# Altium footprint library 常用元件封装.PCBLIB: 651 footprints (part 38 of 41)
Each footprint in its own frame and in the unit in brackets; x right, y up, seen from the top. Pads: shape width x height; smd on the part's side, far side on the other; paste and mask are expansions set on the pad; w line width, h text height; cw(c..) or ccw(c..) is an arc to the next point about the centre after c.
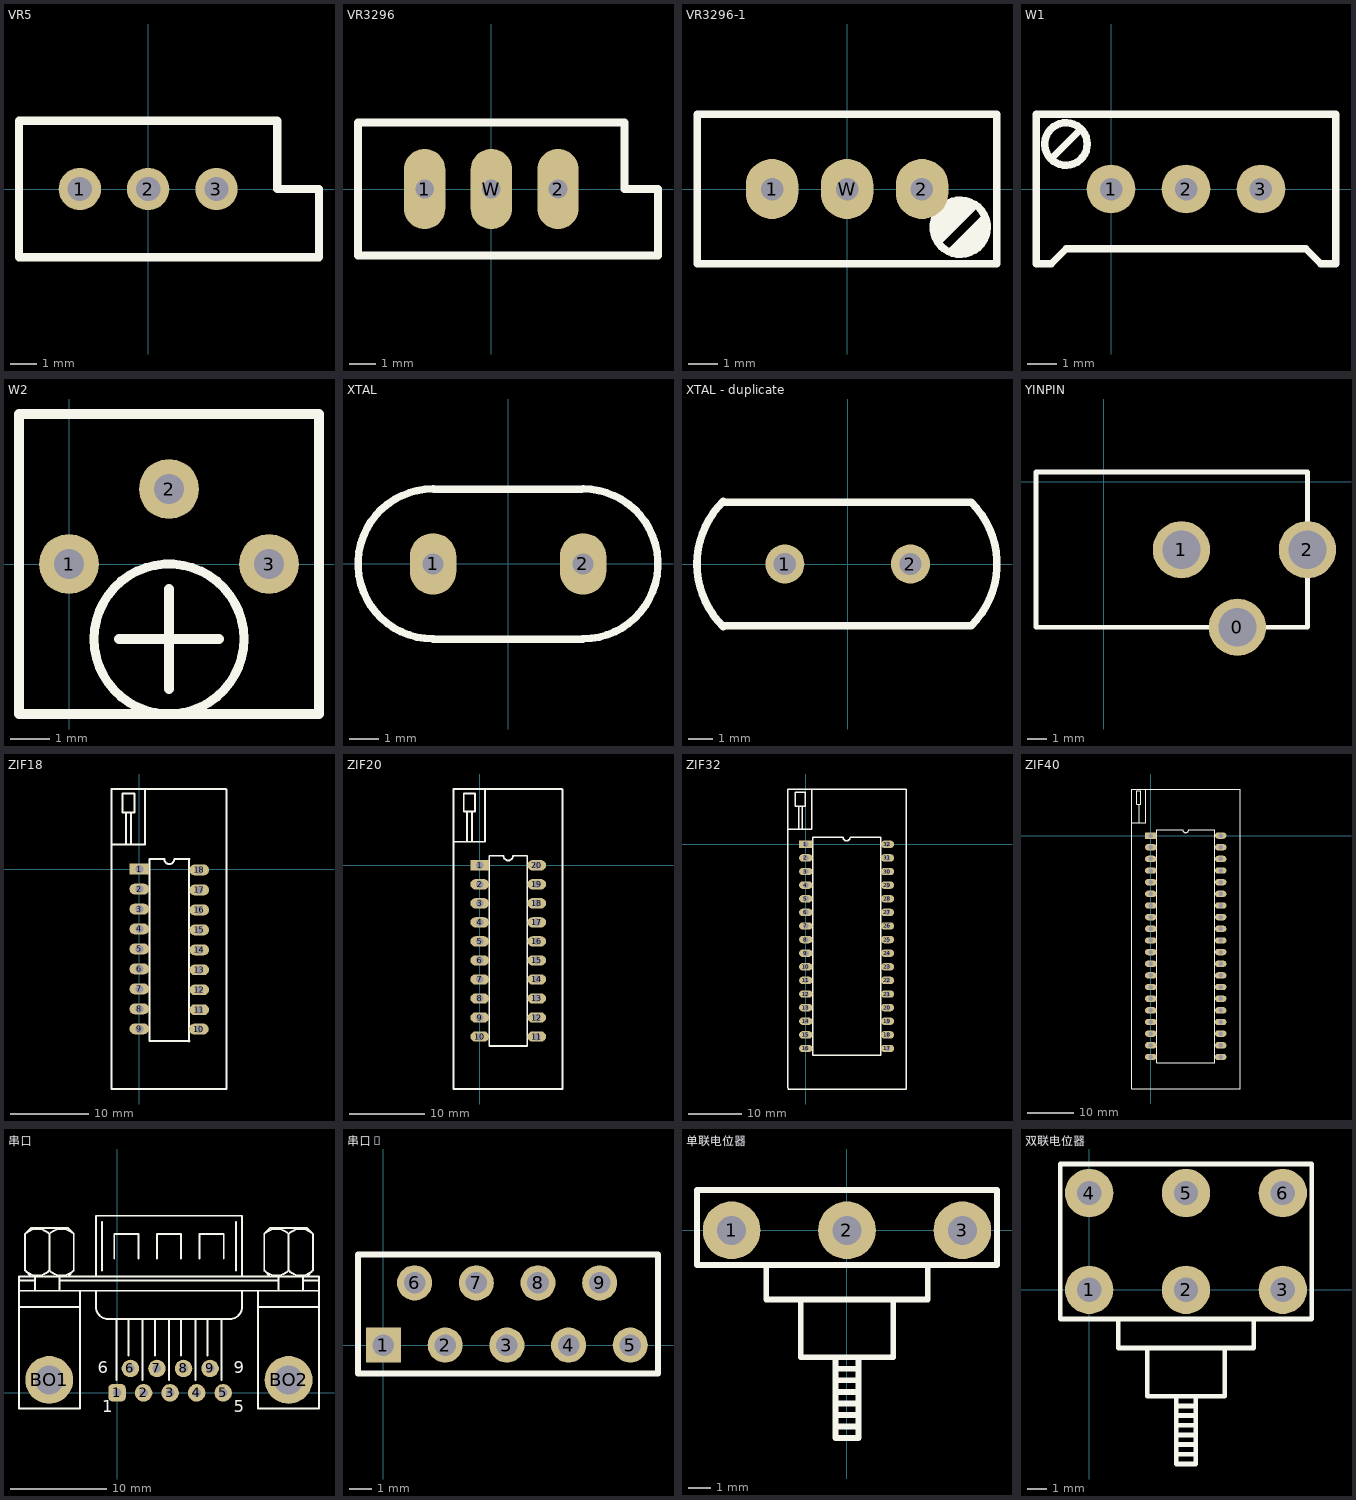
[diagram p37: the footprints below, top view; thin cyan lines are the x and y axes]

## VR5 [mil]
pads (3):
  round 62 hole 35.43: 1(-100,0) 2(0,0) 3(100,0)
TopOverlay:
  lines w12: -188.98,-100 -188.98,100 188.98,100 188.98,0 250,0 250,-100 -188.98,-100

## VR3296 [mil]
pads (3):
  oval 62x120 hole 28: 1(-100,0) 2(100,0) W(0,0)
TopOverlay:
  lines w12: -200,-100 250,-100 250,0 200,0 200,100 -200,100 -200,-100

## VR3296-1 [mil]
pads (3):
  oval 70x80 hole 30: 1(-100,0) 2(100,0) W(0,0)
TopOverlay:
  circle w10: c151,-51 r36.06
  lines w10: 157.76,-74.24 164.24,-74.24 171,-81 ; 171,-21 151,-41 121,-71 121,-61 161,-21 141,-21 ; 172.88,-79.12 171,-81 ; 181,-41 141,-81 151,-81 ; 131,-31 121,-41 121,-51 141,-31 ; 131,-31 141,-21 ; 131,-31 141,-31 ; 141,-31 141,-21 ; 141,-31 151,-31 141,-21 ; 151,-81 171,-81 ; 151,-81 166.82,-65.18 172.88,-65.18 187.06,-51 187.06,-47.06 172.88,-61.23 170.77,-61.23 171,-61.47 171,-81 ; -200,-100 0,-100 200,-100 200,100 -200,100 -200,-100

## W1 [mil] "3296"
pads (3):
  round 65 hole 30: 1(0,0) 2(100,0) 3(200,0)
TopOverlay:
  circle w10: c-60,60 r28.28
  lines w10: -80,40 -40,80 ; -100,-100 -80,-100 -60,-80 260,-80 280,-100 300,-100 300,100 -100,100 -100,-100

## W2 [mil]
pads (3):
  round 60 hole 30: 1(0,0) 2(100,75) 3(200,0)
TopOverlay:
  circle w9: c100,-75 r75
  lines w10: 50,-75 150,-75 ; 100,-125 100,-25 ; -50,-150 250,-150 250,150 -50,150 -50,0 -50,-150

## XTAL [mil]
pads (2):
  oval 62x82 hole 28: 1(-100,0) 2(100,0)
TopOverlay:
  lines w10: -100,-100.39 99.8,-100.39 ; -100,-100 cw(c-100,0) -100,100 ; -99.02,99.41 98.62,99.37 ; 100,-100 ccw(c100,0) 100,100

## XTAL - duplicate [mil]
pads (2):
  round 62 hole 35.43: 1(-100,0) 2(100,0)
TopOverlay:
  lines w12: -198.1,-99.7 cw(c-100,0) -198.1,99.7 ; -196.85,-98.42 196.85,-98.42 ; -196.85,98.42 196.85,98.42 ; 196.59,-98.16 ccw(c100,0) 196.59,98.16

## YINPIN [mm]
pads (3):
  round 3 hole 2: 0(7,-7.62) 1(4.064,-3.556) 2(10.668,-3.556)
TopOverlay:
  lines w0.254: -3.556,-7.62 10.668,-7.62 10.668,0.508 -3.556,0.508 -3.556,-7.62

## ZIF18 [mm]
pads (18):
  rect 2.5x1.38 hole 1: 1(0,0)
  oval 2.5x1.38 hole 1: 2(0,-2.54) 3(0,-5.08) 4(0,-7.62) 5(0,-10.16) 6(0,-12.7) 7(0,-15.24) 8(0,-17.78) 9(0,-20.32) 10(7.578,-20.354) 11(7.62,-17.894) 12(7.62,-15.354) 13(7.62,-12.814) 14(7.62,-10.274) 15(7.62,-7.734) 16(7.62,-5.194) 17(7.62,-2.654) 18(7.62,-0.114)
TopOverlay:
  lines w0.254: -3.535,-27.974 11.007,-27.974 ; -3.535,-27.821 -3.522,-18.236 -3.522,-7.112 -3.522,10.186 -3.252,10.186 11.022,10.186 ; -3.522,3.148 0.726,3.148 0.726,10.15 ; -1.686,3.238 -1.686,7.198 ; -1.038,3.148 -1.038,7.198 ; 6.346,-21.916 6.346,1.249 ; 6.35,-21.895 1.27,-21.895 1.27,1.27 3.175,1.27 ccw(c3.81,1.27) 4.445,1.27 6.35,1.27 ; 11.058,-27.974 11.076,-17.984 11.076,-6.986 11.076,10.132 ; -2.136,7.216 -2.136,9.61 -0.642,9.61 -0.606,9.574 -0.606,7.198 -2.118,7.198 -2.136,7.216

## ZIF20 [mm]
pads (20):
  rect 2.5x1.38 hole 1: 1(0,0)
  oval 2.5x1.38 hole 1: 2(0,-2.54) 3(0,-5.08) 4(0,-7.62) 5(0,-10.16) 6(0,-12.7) 7(0,-15.24) 8(0,-17.78) 9(0,-20.32) 10(0,-22.86) 11(7.62,-22.86) 12(7.62,-20.32) 13(7.62,-17.78) 14(7.62,-15.24) 15(7.62,-12.7) 16(7.62,-10.16) 17(7.62,-7.62) 18(7.62,-5.08) 19(7.62,-2.54) 20(7.62,0)
TopOverlay:
  lines w0.254: -3.522,-29.828 -3.522,-18.236 -3.522,-7.112 -3.522,10.186 -3.252,10.186 11.022,10.186 ; -3.522,3.148 0.726,3.148 0.726,10.15 ; -3.486,-29.864 7.602,-29.864 9.87,-29.864 11.04,-29.864 ; -1.686,3.238 -1.686,7.198 ; -1.038,3.148 -1.038,7.198 ; 11.076,-29.828 11.076,-17.984 11.076,-6.986 11.076,10.132 ; -2.136,7.216 -2.118,7.198 -0.606,7.198 -0.606,9.574 -0.642,9.61 -2.136,9.61 -2.136,7.216 ; 1.27,-24.13 6.35,-24.13 6.35,1.27 4.445,1.27 cw(c3.81,1.27) 3.175,1.27 1.27,1.27 1.27,-24.13

## ZIF32 [mm]
pads (32):
  rect 2.5x1.38 hole 1: 1(0,0)
  oval 2.5x1.38 hole 1: 2(0,-2.54) 3(0,-5.08) 4(0,-7.62) 5(0,-10.16) 6(0,-12.7) 7(0,-15.24) 8(0,-17.78) 9(0,-20.32) 10(0,-22.86) 11(0,-25.4) 12(0,-27.94) 13(0,-30.48) 14(0,-33.02) 15(0,-35.56) 16(0,-38.1) 17(15.24,-38.1) 18(15.24,-35.56) 19(15.24,-33.02) 20(15.24,-30.48) 21(15.24,-27.94) 22(15.24,-25.4) 23(15.24,-22.86) 24(15.24,-20.32) 25(15.24,-17.78) 26(15.24,-15.24) 27(15.24,-12.7) 28(15.24,-10.16) 29(15.24,-7.62) 30(15.24,-5.08) 31(15.24,-2.54) 32(15.24,0)
TopOverlay:
  lines w0.254: -3.322,2.794 1.034,2.794 1.088,2.848 1.088,10.318 ; -3.07,10.318 18.71,10.318 18.71,-2.354 18.71,-7.97 18.71,-45.662 -3.304,-45.662 -3.322,-45.23 -3.322,-9.734 -3.322,-2.444 -3.322,9.922 -3.322,10.318 -2.242,10.318 ; -1.324,2.794 -1.324,7.078 ; -0.694,2.794 -0.694,7.078 ; -1.99,7.078 -1.99,9.706 -0.118,9.706 -0.118,7.078 -1.99,7.078 ; 1.27,-39.37 13.97,-39.37 13.97,1.27 8.255,1.27 cw(c7.62,1.27) 6.985,1.27 1.27,1.27 1.27,-39.37

## ZIF40 [mm]
pads (40):
  rect 2.5x1.38 hole 1: 1(0,0)
  oval 2.5x1.38 hole 1: 2(0,-2.54) 3(0,-5.08) 4(0,-7.62) 5(0,-10.16) 6(0,-12.7) 7(0,-15.24) 8(0,-17.78) 9(0,-20.32) 10(0,-22.86) 11(0,-25.4) 12(0,-27.94) 13(0,-30.48) 14(0,-33.02) 15(0,-35.56) 16(0,-38.1) 17(0,-40.64) 18(0,-43.18) 19(0,-45.72) 20(0,-48.26) 21(15.24,-48.26) 22(15.24,-45.72) 23(15.24,-43.18) 24(15.24,-40.64) 25(15.24,-38.1) 26(15.24,-35.56) 27(15.24,-33.02) 28(15.24,-30.48) 29(15.24,-27.94) 30(15.24,-25.4) 31(15.24,-22.86) 32(15.24,-20.32) 33(15.24,-17.78) 34(15.24,-15.24) 35(15.24,-12.7) 36(15.24,-10.16) 37(15.24,-7.62) 38(15.24,-5.08) 39(15.24,-2.54) 40(15.24,0)
TopOverlay:
  lines w0.254: -4.191,0 -4.191,10.16 19.558,10.16 19.558,0 19.558,-55.245 -1.397,-55.245 ; -4.191,0.762 -4.191,-55.245 -1.27,-55.245 ; -4.064,2.794 -1.143,2.794 -1.143,4.953 -1.143,10.16 ; -2.54,2.794 -2.54,6.858 ; -2.159,6.985 -2.159,6.858 ; -2.159,6.858 -3.048,6.858 -3.048,9.779 -2.159,9.779 -2.159,6.858 ; 1.27,-49.53 13.97,-49.53 13.97,1.27 8.255,1.27 cw(c7.62,1.27) 6.985,1.27 1.27,1.27 1.27,-49.53

## 串口 [mil]
pads (11):
  rrect50% 72x72 hole 35: 1(0,0)
  round 72 hole 35: 2(109.17,0) 3(218.33,0) 4(327.5,0) 5(436.67,0) 6(55,100) 7(164.17,100) 8(273.33,100) 9(382.5,100)
  round 196.67 hole 118.33: BO1(-278.83,53) BO2(705.33,53)
TopOverlay:
  lines w8: -403,353 -153,353 ; -403,419.67 830.33,419.67 ; -403,461.33 -336.33,461.33 ; -378.09,502.91 ccw(c-328,553) -277.91,502.91 ; -378.09,653.09 cw(c-328,603) -277.91,653.09 ; -353,478 -378,503 -378,653 -353,678 -203,678 -178,653 -178,503 -203,478 ; -336.33,419.67 -336.33,478 ; -278.09,502.91 ccw(c-228,553) -177.91,502.91 ; -278.09,653.09 cw(c-228,603) -177.91,653.09 ; -278,503 -278,653 ; -236.33,419.67 -236.33,478 ; -236.33,461.33 663.67,461.33 ; -153,419.67 -153,-63.67 -403,-63.67 -403,478 830.33,478 830.33,-63.67 580.33,-63.67 580.33,419.67 ; -86.33,419.67 -86.33,353 ccw(c-36.33,353) -36.33,303 463.67,303 ccw(c463.67,353) 513.67,353 513.67,419.67 ; -86.33,478 -86.33,728 513.67,728 513.67,478 ; -61.33,503 -61.33,703 ; -11.33,553 -11.33,653 88.67,653 88.67,553 ; -3,53 -3,303 ; 47,153 47,303 ; 105.33,53 105.33,303 ; 155.33,153 155.33,303 ; 163.67,553 163.67,653 263.67,653 263.67,553 ; 213.67,53 213.67,303 ; 263.67,153 263.67,303 ; 322,53 322,303 ; 338.67,553 338.67,653 438.67,653 438.67,553 ; 372,153 372,303 ; 430.33,53 430.33,303 ; 488.67,503 488.67,703 ; 580.33,353 830.33,353 ; 605.25,502.91 ccw(c655.33,553) 705.42,502.91 ; 605.25,653.09 cw(c655.33,603) 705.42,653.09 ; 630.33,478 605.33,503 605.33,653 630.33,678 780.33,678 805.33,653 805.33,503 780.33,478 ; 663.67,419.67 663.67,478 ; 705.25,502.91 ccw(c755.33,553) 805.42,502.91 ; 705.25,653.09 cw(c755.33,603) 805.42,653.09 ; 705.33,503 705.33,653 ; 763.67,419.67 763.67,478 ; 763.67,461.33 830.33,461.33
  text "1" at -60,-80 h50
  text "9" at 480,80 h50
  text "5" at 480,-80 h50
  text "6" at -80,80 h50

## 串口1 [mil]
height 590.55
pads (9):
  rect 62x62 hole 38: 1(0,0)
  round 62 hole 38: 2(109,0) 3(218,0) 4(327,0) 5(436,0) 6(55,110) 7(164,110) 8(273,110) 9(382,110)
TopOverlay:
  lines w10: -45,-50 -45,160 485,160 485,-50 -45,-50

## 单联电位器 [mil]
pads (3):
  round 100 hole 50: 1(-200,0) 2(0,0) 3(200,0)
TopOverlay:
  lines w10: -140,-60 -140,-120 140,-120 140,-60 ; -80,-120 -80,-220 80,-220 80,-120 ; -20,-340 20,-340 ; -20,-320 20,-320 ; -20,-300 20,-300 ; -20,-280 20,-280 ; -20,-260 20,-260 ; -20,-240 20,-240 ; -20,-220 -20,-360 20,-360 20,-220 ; -260,-60 -260,70 260,70 260,-60 -260,-60

## 双联电位器 [mil]
pads (6):
  round 100 hole 50: 1(0,0) 2(200,0) 3(400,0) 4(0,200) 5(200,200) 6(400,200)
TopOverlay:
  lines w10: 60,-60 60,-120 340,-120 340,-60 ; 120,-120 120,-220 280,-220 280,-120 ; 180,-340 220,-340 ; 180,-320 220,-320 ; 180,-300 220,-300 ; 180,-280 220,-280 ; 180,-260 220,-260 ; 180,-240 220,-240 ; 180,-220 180,-360 220,-360 220,-220 ; -60,-60 -60,260 460,260 460,-60 -60,-60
